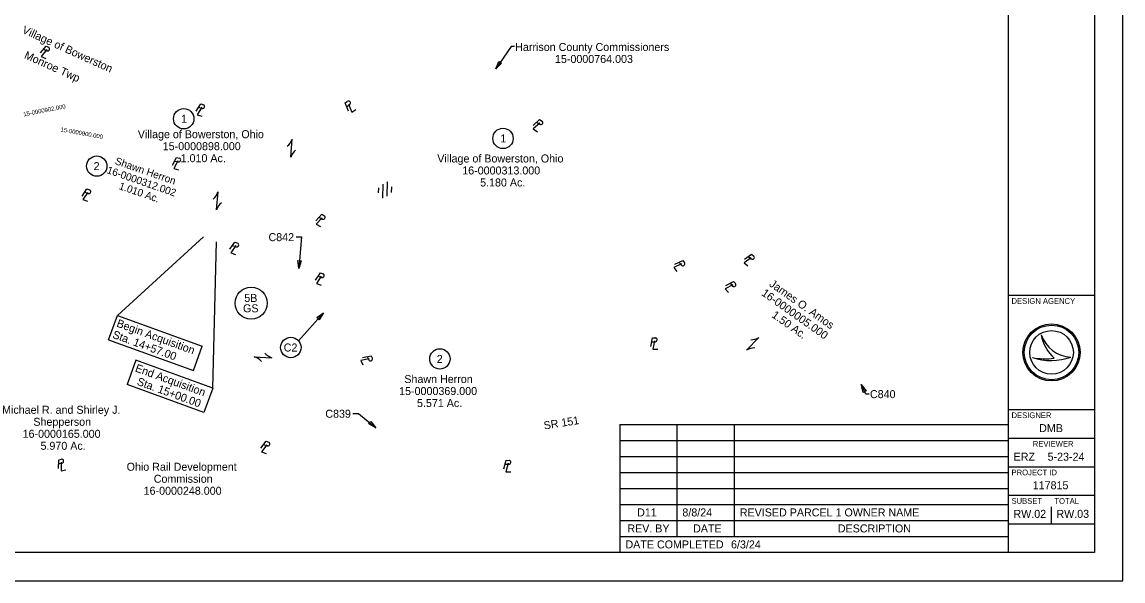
# Model space of a CAD drawing. Extents: x -583 to 3400, y -1921 to 2200.
# Drawn here: x 1474 to 3400, y 0 to 978 of the extents above; entities that cross this region are included whole.
import ezdxf

# ---------------------------------------------------------------- set-up
doc = ezdxf.new("R2010")
doc.units = 0
for name, color, linetype in [('DR_X_Elev_Flow', 7, 'Continuous'), ('SH_Border', 7, 'Continuous'), ('SH_Cut_Line', 7, 'Continuous'), ('SH_Data', 7, 'Continuous'), ('SH_Text', 7, 'Continuous'), ('UT_X_Misc_Cells', 7, 'Continuous')]:
    doc.layers.add(name, color=color, linetype=linetype)

msp = doc.modelspace()

# ---------------------------------------------------------------- linework, layer by layer
at = {"layer": 'DR_X_Elev_Flow'}
for p, q in [((2105.2, 670.2), (2106, 694.4)), ((2112.8, 673.5), (2113.6, 698.8)), ((2098, 679.4), (2098.3, 688.3)), ((2120.5, 679.6), (2120.8, 689.6))]:
    msp.add_line(p, q, dxfattribs=at)
at = {"layer": 'SH_Border'}
for p, q in [((3200, 50), (3200, 2150)), ((3200, 500), (3350, 500)), ((3200, 300), (3350, 300)), ((3200, 250), (3350, 250)), ((3200, 200), (3350, 200)), ((3200, 150), (3350, 150)), ((3200, 100), (3350, 100))]:
    msp.add_line(p, q, dxfattribs=at)
msp.add_lwpolyline([(150, 2150), (3350, 2150), (3350, 50), (150, 50)], close=True, dxfattribs=at)
at = {"layer": 'SH_Cut_Line'}
msp.add_lwpolyline([(0, 0), (3400, 0), (3400, 2200), (0, 2200)], close=True, dxfattribs=at)
at = {"layer": 'SH_Data'}
for p, q in [((3256.7, 431), (3256.7, 431)), ((3241.7, 391), (3241.7, 391)), ((3275, 400), (3275, 400)), ((3308.7, 391.9), (3308.7, 391.9)), ((3275, 100), (3275, 130))]:
    msp.add_line(p, q, dxfattribs=at)
for radius in [50, 47.7, 47.7, 38.2]:
    msp.add_circle((3275, 400), radius, dxfattribs=at)
for centre, radius, start, end in [((3311.6, 449.8), 58, 198.9257, 198.9319), ((3334.7, 447), 79.6, 191.6379, 191.6421), ((3311.6, 449.8), 58, 198.9319, 267.1657), ((3334.7, 447), 79.6, 191.6421, 226.0947), ((3273.9, 487), 101.3, 251.4576, 290.0832), ((3264.8, 515.4), 126.6, 259.4964, 259.4995), ((3273.9, 487), 101.3, 251.4527, 251.4576), ((3264.8, 515.4), 126.6, 259.4995, 276.6672)]:
    msp.add_arc(centre, radius, start, end, dxfattribs=at)
at = {"layer": 'SH_Text'}
for p, q in [((2329.8, 935.1), (2302.7, 896.2)), ((2335.5, 935.1), (2329.8, 935.1)), ((1641, 464.7), (1791.6, 602.2)), ((1807.7, 337.6), (1814.2, 593.6)), ((1625.5, 422.2), (1641, 464.7)), ((1641, 464.7), (1789.5, 410.7)), ((1957.7, 420.4), (2001.4, 469.5)), ((1625.5, 422.2), (1774, 368.2)), ((1774, 368.2), (1789.5, 410.7)), ((1673.3, 386.5), (1657.9, 344)), ((1807.7, 337.6), (1673.3, 386.5)), ((1792.2, 295.1), (1657.9, 344)), ((1807.7, 337.6), (1792.2, 295.1)), ((2519.7, 274), (2519.7, 50)), ((2519.7, 274), (3200, 274)), ((2619.7, 274), (2619.7, 78)), ((2719.7, 274), (2719.7, 78)), ((2519.7, 246), (3200, 246)), ((2519.7, 218), (3200, 218)), ((2519.7, 190), (3200, 190)), ((2519.7, 162), (3200, 162)), ((2519.7, 134), (3200, 134)), ((2519.7, 106), (3200, 106)), ((2519.7, 78), (3200, 78)), ((3200, 50), (3200, 50))]:
    msp.add_line(p, q, dxfattribs=at)
for points in [[(2308.4, 909.3), (2313, 906.1), (2302.7, 896.2)], [(1956.6, 560.9), (1962.2, 560.4), (1958.1, 546.8)], [(1994.2, 457.2), (1990, 460.9), (2001.4, 469.5)], [(2950.6, 332.5), (2945.5, 330), (2941.9, 343.8)], [(2080.6, 274.9), (2084.1, 279.2), (2093.3, 268.3)]]:
    msp.add_lwpolyline(points, close=True, dxfattribs=at)
for points in [[(1953.5, 602), (1963.2, 602), (1958.1, 546.8)], [(2956.3, 327), (2950.1, 327), (2941.9, 343.8)], [(2052.9, 292.9), (2062.6, 292.9), (2093.3, 268.3)]]:
    msp.add_lwpolyline(points, dxfattribs=at)
for centre, radius in [((1757, 808.9), 17.8), ((2315.5, 774.5), 17.8), ((1604.9, 726), 17.8), ((1875, 486.2), 28), ((1944.4, 408.6), 17.8), ((2205.1, 388.6), 17.8)]:
    msp.add_circle(centre, radius, dxfattribs=at)
at = {"layer": 'UT_X_Misc_Cells'}
for p, q in [((1511.8, 930.7), (1517.7, 928)), ((1514.1, 926.2), (1514.1, 926.2)), ((1782.9, 828.9), (1789.1, 826.9)), ((2042.1, 830.1), (2047.4, 833.9)), ((2047.2, 829.9), (2047.2, 829.9)), ((1785.8, 824.7), (1785.8, 824.7)), ((2374.4, 802.8), (2379.9, 799.3)), ((2376.1, 798), (2376.1, 798)), ((1944.3, 741.9), (1946.6, 773)), ((1945.5, 757.4), (1945.5, 757.4)), ((1741.2, 734.8), (1747.5, 733.4)), ((1744.4, 730.9), (1744.4, 730.9)), ((1583.8, 680.2), (1589.9, 678)), ((1586.5, 675.9), (1586.5, 675.9)), ((1814.6, 649.6), (1817, 680.8)), ((1815.8, 665.2), (1815.8, 665.2)), ((1993.7, 636.5), (1999.4, 633.4)), ((1995.8, 631.8), (1995.8, 631.8)), ((1842.6, 587.2), (1848.7, 585)), ((1845.3, 582.9), (1845.3, 582.9)), ((2744.6, 567.9), (2749.6, 563.7)), ((2745.7, 562.9), (2745.7, 562.9)), ((2623.3, 557.8), (2627.5, 552.8)), ((2623.5, 552.7), (2623.5, 552.7)), ((1992.2, 533.4), (1998.3, 531.2)), ((1994.9, 529.1), (1994.9, 529.1)), ((2712.7, 520.9), (2717.1, 516.2)), ((2713.1, 515.9), (2713.1, 515.9)), ((2741.4, 403.8), (2763.3, 426.2)), ((2575.5, 418.4), (2582, 418.8)), ((2579.7, 415.5), (2579.7, 415.5)), ((2752.3, 415), (2752.3, 415)), ((1880.2, 392.3), (1911.4, 390.7)), ((1895.8, 391.5), (1895.8, 391.5)), ((2076.7, 387.9), (2076.7, 387.9)), ((2077.7, 392.8), (2080.6, 387)), ((1896.8, 238.9), (1902.9, 236.5)), ((1899.4, 234.6), (1899.4, 234.6)), ((1538.1, 205), (1544.4, 206.5)), ((1542.7, 202.9), (1542.7, 202.9)), ((2319.2, 204.4), (2325.7, 204.3)), ((2323.1, 201.2), (2323.1, 201.2))]:
    msp.add_line(p, q, dxfattribs=at)
for points in [[(1506.6, 924.3), (1516.2, 936.2), (1520.9, 934.1)], [(1517.3, 930), (1507.6, 918.1), (1515.6, 914.6)], [(1778.6, 821.9), (1786.7, 834.9), (1791.6, 833.4)], [(1788.5, 828.9), (1780.4, 815.9), (1788.7, 813.4)], [(2045, 822.4), (2039.6, 836.7), (2043.8, 839.7)], [(2045.5, 834.6), (2050.8, 820.2), (2057.9, 825.3)], [(2368.4, 797.2), (2379.6, 807.6), (2383.9, 804.9)], [(2379.8, 801.4), (2368.5, 791), (2375.9, 786.3)], [(1737.4, 727.6), (1744.5, 741.1), (1749.5, 740)], [(1746.8, 735.3), (1739.6, 721.8), (1748.1, 719.8)], [(1579.1, 673.4), (1587.8, 686.1), (1592.6, 684.3)], [(1589.4, 680), (1580.6, 667.4), (1588.8, 664.5)], [(1988.1, 630.4), (1998.6, 641.7), (2003.1, 639.2)], [(1999.2, 635.4), (1988.8, 624.2), (1996.5, 620.1)], [(1837.9, 580.4), (1846.6, 593), (1851.5, 591.3)], [(1848.2, 587), (1839.4, 574.4), (1847.7, 571.4)], [(2615.9, 554.3), (2629.8, 560.8), (2633.1, 556.8)], [(2749.8, 565.7), (2737.3, 557), (2743.9, 551.3)], [(2737.9, 563.1), (2750.4, 572), (2754.4, 568.6)], [(1987.5, 526.6), (1996.2, 539.3), (2001, 537.5)], [(2628, 554.8), (2614.2, 548.4), (2619.7, 541.6)], [(1997.7, 533.2), (1989, 520.6), (1997.2, 517.7)], [(2705.4, 517), (2718.9, 524.3), (2722.4, 520.6)], [(2717.5, 518.2), (2704.1, 511), (2710, 504.6)], [(2573.9, 410.3), (2576.9, 425.4), (2582, 425.7)], [(2580.7, 420.4), (2577.7, 405.4), (2586.4, 405.9)], [(2081.6, 388.8), (2066.6, 385.8), (2070.4, 378)], [(2069.7, 391.2), (2084.7, 394.2), (2087, 389.6)], [(1891.9, 232.3), (1901, 244.6), (1905.8, 242.7)], [(1902.4, 238.5), (1893.3, 226.2), (1901.4, 223)], [(1537.9, 196.8), (1538.3, 212.1), (1543.3, 213.3)], [(1542.9, 207.9), (1542.5, 192.6), (1551, 194.6)], [(2316.9, 196.5), (2321.1, 211.3), (2326.3, 211.1)], [(2324.5, 206), (2320.3, 191.3), (2329, 191.1)]]:
    msp.add_lwpolyline(points, dxfattribs=at)
for centre, radius, start, end in [((1519.1, 931.2), 3.45, 246.2378, 57.0949), ((1790.1, 830.3), 3.45, 253.3211, 64.1782), ((2045.4, 836.6), 3.45, 305.9051, 116.7622), ((2381.7, 802.3), 3.45, 238.095, 48.9521), ((1921.3, 781.4), 26.7, 309.1286, 341.7711), ((1969.6, 733.5), 26.7, 129.1286, 161.7711), ((1748.3, 736.8), 3.45, 257.6297, 68.4869), ((1591, 681.3), 3.45, 250.6989, 61.556), ((1791.6, 689.1), 26.7, 309.1286, 341.7711), ((1839.9, 641.3), 26.7, 129.1286, 161.7711), ((2001, 636.5), 3.45, 242.342, 53.1991), ((1849.8, 588.2), 3.45, 250.6989, 61.556), ((2751.8, 566.4), 3.45, 230.3906, 41.2477), ((2630.1, 555.1), 3.45, 220.2943, 31.1515), ((1999.4, 534.5), 3.45, 250.6989, 61.556), ((2719.6, 518.6), 3.45, 223.7165, 34.5736), ((2581.7, 422.2), 3.45, 274.0163, 84.8734), ((2749.2, 448.9), 26.7, 269.1353, 301.7779), ((2755.5, 381.2), 26.7, 89.1353, 121.7779), ((1872.5, 366.8), 26.7, 40.5034, 73.1459), ((1919.1, 416.2), 26.7, 220.5034, 253.1459), ((2083.7, 388.5), 3.45, 206.5322, 17.3893), ((1904.1, 239.8), 3.45, 248.8406, 59.6977), ((1543.6, 209.8), 3.45, 283.7906, 94.6477), ((2325.7, 207.7), 3.45, 269.3347, 80.1918)]:
    msp.add_arc(centre, radius, start, end, dxfattribs=at)

# ---------------------------------------------------------------- texts
at = {"layer": 'SH_Data'}
for s, height, p in [('DESIGN AGENCY', 10, (3205, 485)), ('DESIGNER', 10, (3205, 285)), ('DMB', 14, (3253.3, 260.5)), ('REVIEWER', 10, (3242.2, 235)), ('ERZ', 14, (3208.7, 210.5)), ('5-23-24', 14, (3268.1, 210.5)), ('PROJECT ID', 10, (3205, 185)), ('117815', 14, (3242.1, 160.5)), ('SUBSET', 10, (3205, 135)), ('TOTAL', 10, (3280, 135)), ('RW.02', 14, (3208.4, 110.5)), ('RW.03', 14, (3283.5, 110.5))]:
    msp.add_text(s, height=height, dxfattribs=at).set_placement(p)
at = {"layer": 'SH_Text'}
for s, height, rotation, p in [('Village of Bowerston', 14, 335.7668, (1473.1, 959.4)), ('Monroe Twp', 14, 335.7668, (1476.8, 915.3)), ('15-0000902.000', 7.468, 10.9284, (1477.2, 813)), ('15-0000900.000', 7.468, 349.8103, (1541.1, 786.8)), ('Shawn Herron', 12.981, 340.8755, (1635.7, 729.7)), ('16-0000312.002', 12.981, 340.8755, (1621.5, 714)), ('1.010 Ac.', 12.98, 340.8755, (1642.5, 686.1)), ('James O. Amos', 14, 324.6408, (2780, 517.1)), ('16-0000005.000', 14, 324.6408, (2766.5, 501)), ('1.50 Ac.', 14, 324.6408, (2784.3, 462.6)), ('Begin Acquisition', 14, 340.0122, (1638.4, 445.5)), ('Sta. 14+57.00', 14, 340.0122, (1631.2, 425.7)), ('End Acquisition', 14, 340.0122, (1670.9, 367)), ('Sta. 15+00.00', 14, 340.0122, (1674.1, 343.5)), ('SR 151', 14, 9.0183, (2387.8, 265))]:
    msp.add_text(s, height=height, rotation=rotation, dxfattribs=at).set_placement(p)
for s, p in [('Harrison County Commissioners', (2336.9, 927.5)), ('15-0000764.003', (2406.4, 906.5)), ('1', (1752.4, 801.9)), ('Village of Bowerston, Ohio', (1676.7, 774.9)), ('1', (2310.8, 767.5)), ('15-0000898.000', (1720.3, 753.9)), ('2', (1599.4, 719)), ('1.010 Ac.', (1751.6, 732.9)), ('Village of Bowerston, Ohio', (2200.6, 732.4)), ('16-0000313.000', (2244.2, 711.4)), ('5.180 Ac.', (2275.5, 690.4)), ('C842', (1905.3, 594.7)), ('5B', (1863, 488.3)), ('GS', (1860.8, 470.2)), ('C2', (1931.9, 401.6)), ('2', (2199.6, 381.6)), ('Shawn Herron', (2142.9, 346.4)), ('15-0000369.000', (2133.8, 325.4)), ('C840', (2957.4, 320)), ('5.571 Ac.', (2165.1, 304.4)), ('Michael R. and Shirley J.', (1439.3, 292.6)), ('C839', (2004.7, 285.7)), ('Shepperson', (1494, 271.6)), ('16-0000165.000', (1475.2, 250.6)), ('5.970 Ac.', (1506.5, 229.6)), ('Ohio Rail Development', (1657.2, 192.9)), ('Commission', (1704.6, 171.9)), ('16-0000248.000', (1686.9, 150.9)), ('D11', (2550.1, 113)), (' 8/8/24 ', (2624.1, 113)), ('REVISED PARCEL 1 OWNER NAME           ', (2729.7, 113)), ('REV. BY', (2533, 85)), ('DATE', (2648, 85)), ('DESCRIPTION', (2901.2, 85)), ('DATE COMPLETED', (2529.7, 57)), ('6/3/24                             ', (2714.4, 57))]:
    msp.add_text(s, height=14, dxfattribs=at).set_placement(p)

doc.saveas('drawing.dxf')
